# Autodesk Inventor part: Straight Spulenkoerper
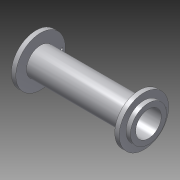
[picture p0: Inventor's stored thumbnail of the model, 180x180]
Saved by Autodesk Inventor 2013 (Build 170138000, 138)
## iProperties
Created: 2012-07
Part Number: Straight Spulenkoerper
Material: PC/ABS-Kunststoff
Document SubType Name: Modeling
Designer: rYan
Density: 1.493 g/cm^3
Mass: 4.13238 g
Surface Area: 51.7802 cm^2
Volume: 2.76784 cm^3
Author: rYan
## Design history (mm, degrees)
sketch "Skizze1"
  geometry: L1 (-26, 0)-(-26, 8); L2 (-26, 8)-(-24, 8); L3 (-24, 8)-(-24, 11); L4 (-24, 11)-(-22, 11); L5 (-22, 11)-(-22, 6.25); L6 (-22, 6.25)-(22, 6.25); L7 (22, 6.25)-(22, 11); L8 (22, 11)-(24, 11); L9 (26, 8)-(26, 0); L10 (26, 0)-(-26, 0); L11 (0, 0)-(0, 6.25); L12 (24, 11)-(24, 8); L13 (24, 8)-(26, 8); L14 (-36.4, 0)-(36.4, 0) reference
  constraints: 26 end point, 9 parallel, 3 perpendicular, 1 collinear, 1 midpoint, 1 vertical, 5 other
  dimensions: "d0" = 16 diameter of L2 L10; "d2" = 22 diameter of L4 L10; "d3" = 2 distance between parallel lines of L1 L3; "d4" = 2 distance between parallel lines of L5 L3; "d5" = 12.5 diameter of L6 L10; "d6" = 52 distance between parallel lines of L9 L1
revolve "Umdrehung1" sketch "Skizze1" stored, may be unused: angle "d7" = 90 deg
sketch "Skizze2"
  geometry: C1 r 8 at (0, 0) reference; 2 further points
  constraints: 1 coincident
hole "Bohrung1" sketch "Skizze2" at (0, 0) diameter "d8" = 11.4; stored, may be unused: countersink angle "d12" = 90 deg, drill point angle "d14" = 118 deg; dims "d9" = 6, "d10" = 4, "d11" = 2, "d13" = 8
sketch "Sketch3"
  geometry: L1 (0, -15.4)-(0, 15.4) reference; 4 further points
  constraints: 2 point on line, 1 vertical alignment, 1 other
  dimensions: "d15" = 1.5 distance of point (0, 9.5) point (0, 8)
hole "Hole2" sketch "Sketch3" at (0, 9.5) diameter "d16" = 1; stored, may be unused: countersink angle "d20" = 90 deg, drill point angle "d22" = 118 deg; dims "d17" = 6, "d18" = 4, "d19" = 2, "d21" = 8
node "Volumenkörper1"
